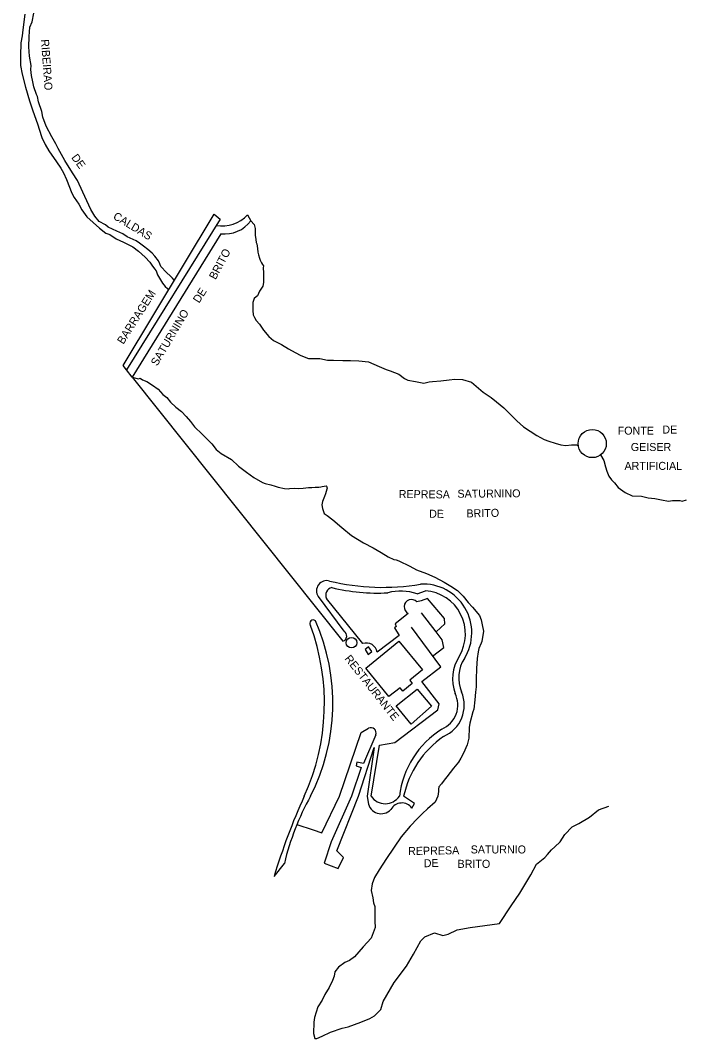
# Model space of a CAD drawing. Extents: x 325899 to 364828, y 7568995 to 7592502.
# Drawn here: x 339741 to 340074, y 7586381 to 7586890 of the extents above; entities that cross this region are included whole.
import ezdxf

# ---------------------------------------------------------------- set-up
doc = ezdxf.new("R2010")
doc.units = 0
for name, color, linetype in [('EDIFEXISTENT', 7, 'Continuous'), ('EDIFIDENTIF', 7, 'Continuous'), ('EDIFOBRAEXIS', 7, 'Continuous')]:
    doc.layers.add(name, color=color, linetype=linetype)

msp = doc.modelspace()

# ---------------------------------------------------------------- linework, layer by layer
at = {"layer": 'EDIFEXISTENT'}
for p, q in [((339792.51, 7586717.06), (339837.9, 7586792.71)), ((339837.9, 7586792.71), (339837.9, 7586792.71)), ((339837.9, 7586792.71), (339837.9, 7586792.71)), ((339837.9, 7586792.71), (339840.97, 7586790.2)), ((339854.7, 7586792.37), (339856.25, 7586789.42)), ((339840.97, 7586790.2), (339794.15, 7586714.93)), ((339841.37, 7586782.96), (339797.06, 7586711.32)), ((339792.51, 7586717.06), (339792.51, 7586717.06)), ((339794.15, 7586714.93), (339792.51, 7586717.06)), ((339797.06, 7586711.32), (339794.15, 7586714.93)), ((339913.76, 7586565.82), (339930.31, 7586579.38)), ((339930.31, 7586579.38), (339942.06, 7586565.04)), ((339925.28, 7586551.76), (339913.76, 7586565.82)), ((339942.06, 7586565.04), (339935.69, 7586559.82)), ((339937.01, 7586558.21), (339932.34, 7586554.38)), ((339935.69, 7586559.82), (339937.01, 7586558.21)), ((339930.97, 7586556.06), (339925.28, 7586551.76)), ((339932.34, 7586554.38), (339930.97, 7586556.06))]:
    msp.add_line(p, q, dxfattribs=at)
msp.add_circle((340026.92, 7586678.11), 7.03, dxfattribs=at)
for centre, radius, start, end in [((339841.76, 7586804.8), 17.94, 261.2223, 316.1329), ((339843.33, 7586798.82), 15.98, 262.9776, 323.9631)]:
    msp.add_arc(centre, radius, start, end, dxfattribs=at)
at = {"layer": 'EDIFOBRAEXIS'}
for points in [[(339743.36, 7586892.73), (339742.33, 7586884.86), (339741.95, 7586881.84), (339741.33, 7586878.4), (339741.21, 7586871.81), (339741.12, 7586867.04), (339741.96, 7586862.61), (339743.75, 7586856.21), (339745.67, 7586849.31), (339747.25, 7586844.92), (339749.77, 7586837.39), (339750.47, 7586835.17), (339751.91, 7586830.98), (339753.52, 7586827.6), (339755.3, 7586824.36), (339759.26, 7586818.94), (339761.35, 7586815.68), (339762.63, 7586813.39), (339764.16, 7586810.11), (339766.92, 7586803.28), (339768.08, 7586801.11), (339770.27, 7586797.65), (339771.8, 7586794.9), (339774.4, 7586791.34), (339780.69, 7586785.81), (339783.78, 7586783.3), (339785.86, 7586782.55), (339789.02, 7586780.35), (339792.73, 7586778.81), (339797.37, 7586776.35), (339800.15, 7586774.19), (339803.45, 7586771.23), (339805.76, 7586768.73), (339806.9, 7586767.32), (339808.2, 7586765.42), (339808.98, 7586764.41), (339809.73, 7586762.37), (339810.6, 7586760.68), (339812.19, 7586758.2), (339813.46, 7586756.52), (339814.62, 7586755.65), (339815.32, 7586755.1)], [(339818.03, 7586759.75), (339817.17, 7586760.75), (339816.22, 7586761.77), (339814.1, 7586763.51), (339811.38, 7586766.59), (339810.85, 7586767.95), (339810.19, 7586769.44), (339808.27, 7586771.69), (339807.07, 7586773.3), (339804.86, 7586775.11), (339802.72, 7586776.8), (339800.64, 7586778.31), (339799.02, 7586779.4), (339794.46, 7586781.46), (339792.38, 7586782.82), (339789.31, 7586784.21), (339784.95, 7586786.27), (339783.59, 7586787.36), (339780.46, 7586788.98), (339778.3, 7586791.72), (339776.31, 7586795.14), (339774.36, 7586799.34), (339772.33, 7586803.75), (339769.71, 7586809.57), (339767.18, 7586813.44), (339763.36, 7586819.57), (339759.98, 7586825.56), (339758.8, 7586827.9), (339756.78, 7586831.4), (339754.05, 7586836.68), (339752.42, 7586841.12), (339751.81, 7586844.01), (339750.18, 7586848.86), (339749.62, 7586851.57), (339749.25, 7586852.47), (339747.79, 7586856.28), (339747.33, 7586858.87), (339746.72, 7586862.08), (339746.39, 7586865.05), (339746.45, 7586867.05), (339745.66, 7586871.66), (339745.28, 7586876.36), (339745.44, 7586881.57), (339745.79, 7586886.22), (339747.06, 7586888.78), (339747.9, 7586893.24)], [(339856.25, 7586789.42), (339858.01, 7586787.6), (339858.47, 7586785.62), (339858.51, 7586782.17), (339858.82, 7586780.14), (339858.95, 7586778.55), (339859.22, 7586777.87), (339859.67, 7586775.51), (339859.85, 7586773.81), (339860.1, 7586772.47), (339860.59, 7586770.75), (339861.01, 7586769.69), (339861.69, 7586768.41), (339862.14, 7586767.58), (339862.71, 7586766.95), (339862.53, 7586765.83), (339862.6, 7586763.34), (339862.67, 7586760.65), (339862.7, 7586758.77), (339862.42, 7586757.65), (339862.31, 7586756.71), (339860.67, 7586754.29), (339859.59, 7586751.96), (339859.04, 7586751.45), (339857.97, 7586750.56), (339857.27, 7586748.54), (339857.35, 7586746.79), (339857.23, 7586744.61), (339857.47, 7586742.5), (339858.08, 7586741.04), (339859, 7586739.63), (339860.63, 7586737.83), (339862.71, 7586734.8), (339865.26, 7586731.59), (339867.58, 7586729.55), (339871.6, 7586727.59), (339875.17, 7586725.46), (339878.48, 7586723.57), (339881.33, 7586722.14), (339885.16, 7586720.66), (339888.13, 7586720.66), (339890.83, 7586720.66), (339894.7, 7586719.84), (339897.57, 7586719.81), (339902.3, 7586719.66), (339906.09, 7586719.53), (339910.3, 7586719.4), (339915.06, 7586718.87), (339920.36, 7586716.55), (339924, 7586715.09), (339925.86, 7586714.41), (339928.11, 7586713.61), (339930.23, 7586712.76), (339933.12, 7586710.55), (339934.83, 7586709.74), (339938.63, 7586709.05), (339942.78, 7586708.31), (339945.44, 7586708.89), (339947.06, 7586709.04), (339951.22, 7586709.42), (339955.4, 7586709.9), (339958.24, 7586710.31), (339962.05, 7586710.19), (339966.57, 7586708.83), (339972.4, 7586703.82), (339976.36, 7586701.15), (339979.14, 7586698.94), (339982.7, 7586695.98), (339989.19, 7586689.41), (339992.64, 7586686.5), (339999.2, 7586682.07), (340002.89, 7586680.12), (340005.19, 7586679.35), (340008.41, 7586678.31), (340011.19, 7586677.4), (340013.77, 7586677.06), (340016.63, 7586677.47), (340018.05, 7586677.44), (340019.12, 7586677.46), (340020.07, 7586676.99)], [(339797.06, 7586711.32), (339800.17, 7586710.49), (339801, 7586710.81), (339802.21, 7586710.01), (339804.29, 7586709.14), (339807.19, 7586707.36), (339809.99, 7586705.22), (339812.4, 7586702.57), (339814.28, 7586701.08), (339816.17, 7586698.85), (339818.78, 7586696.36), (339821.67, 7586694.15), (339823.95, 7586691.6), (339826.2, 7586689.07), (339828.1, 7586686.44), (339832.03, 7586682.77), (339836.89, 7586678.01), (339839.04, 7586675.15), (339841.49, 7586673.06), (339846.62, 7586670.12), (339850.06, 7586666.81), (339854.15, 7586663.73), (339857.81, 7586661.13), (339862.12, 7586658.66), (339863.47, 7586658.2), (339866.23, 7586657.41), (339868.45, 7586656.74), (339869.98, 7586656.39), (339873.06, 7586655.7), (339874.95, 7586655.51), (339875.71, 7586655.62), (339877.99, 7586655.81), (339880.15, 7586655.65), (339882.39, 7586655.74), (339883.73, 7586655.91), (339885.15, 7586656.09), (339886.82, 7586656.15), (339888.47, 7586656.25), (339890.25, 7586656.33), (339891.26, 7586656.43), (339891.9, 7586656.64), (339893.01, 7586656.86), (339893.97, 7586657.03), (339894.2, 7586656.78), (339894.5, 7586655.85), (339894.23, 7586655.26), (339893.56, 7586653.01), (339893.05, 7586651.68), (339892.18, 7586649.15), (339891.75, 7586647.44), (339892.09, 7586645.62), (339892.94, 7586643.12), (339894.46, 7586642.08), (339897.24, 7586639.97), (339901.83, 7586636.11), (339906.55, 7586632.13), (339912.61, 7586628.48), (339917.4, 7586625.97), (339921.38, 7586623.73), (339925.02, 7586621.56), (339927.74, 7586620.23), (339928.86, 7586619.95), (339930.31, 7586619.59), (339935.82, 7586616.85), (339939.08, 7586615.07), (339944.12, 7586613.26), (339948.24, 7586611.35), (339952.86, 7586608.79), (339956.32, 7586606.87), (339959.66, 7586604.74), (339962.45, 7586601.89), (339964.97, 7586598.74), (339967.07, 7586596.39), (339970.57, 7586592.21), (339971.4, 7586590.04), (339971.97, 7586587.61), (339972.59, 7586584.32), (339971.79, 7586579.27), (339971.35, 7586578.33), (339970.3, 7586575.77), (339969.85, 7586573.96), (339969.4, 7586570.67), (339969.1, 7586565.79), (339968.99, 7586560.33), (339968.86, 7586556.54), (339968.57, 7586553.84), (339968.31, 7586550.05), (339967.68, 7586545.47), (339967.32, 7586544.09), (339965.77, 7586538.37), (339965.4, 7586536.26), (339965.27, 7586530.97), (339964.39, 7586527.5), (339962.58, 7586523.48), (339961.2, 7586520.87), (339960.04, 7586518.94), (339957.58, 7586515.85), (339954.2, 7586511.6), (339952.88, 7586509.88), (339951.52, 7586508.1), (339950.25, 7586506.56), (339950.02, 7586505.46), (339950.06, 7586504.29), (339949.78, 7586501.91)], [(339797.06, 7586711.32), (339902.34, 7586579.4)], [(340031.09, 7586672.51), (340032.72, 7586669.57), (340033.56, 7586666.44), (340034.16, 7586664.26), (340035.16, 7586661.84), (340036.62, 7586660.06), (340038.09, 7586658.49), (340039.94, 7586656.11), (340043.41, 7586653.58), (340046.87, 7586652.06), (340051.57, 7586651.79), (340054.86, 7586650.93), (340058.15, 7586650.61), (340061.56, 7586649.91), (340065, 7586649.38), (340067, 7586649.6), (340069.42, 7586649.64), (340070.66, 7586649.66), (340071.93, 7586649.4), (340074.11, 7586650)], [(339939.42, 7586602.99), (339943.53, 7586604.56)], [(339889.99, 7586601.64), (339902.86, 7586584.37)], [(339912.29, 7586578.21), (339894.07, 7586600.75)], [(339948.9, 7586583.98), (339953.3, 7586587.99), (339953.05, 7586590.68), (339944.59, 7586600.77), (339941.41, 7586599.54), (339939.29, 7586598.97)], [(339934.97, 7586593.23), (339928.4, 7586588.04), (339928.88, 7586586.78), (339928.13, 7586586.08), (339930.43, 7586582.28), (339919.43, 7586573.84)], [(339947.17, 7586571.95), (339952.72, 7586576.14), (339951.86, 7586579.99), (339948.9, 7586583.98), (339941.61, 7586593.6)], [(339916.43, 7586501.91), (339920.65, 7586527.37), (339928.32, 7586528.78), (339949.78, 7586544.98), (339950.46, 7586547.99), (339941.71, 7586559.26), (339951.18, 7586566.49), (339936.56, 7586586.4)], [(339902.34, 7586579.4), (339902.34, 7586579.4)], [(339915.09, 7586576.58), (339913.41, 7586575.18), (339914.95, 7586572.72), (339916.76, 7586574.22), (339915.09, 7586576.58)], [(339939.46, 7586555.39), (339946.62, 7586546.93), (339936.47, 7586537.86), (339928.99, 7586547.03), (339928.99, 7586547.03)], [(339928.99, 7586547.03), (339939.46, 7586555.39)], [(339900.62, 7586501.91), (339911.37, 7586533.79), (339915.17, 7586535.96)], [(339918.81, 7586532.6), (339912.61, 7586518.17), (339909.24, 7586518.84), (339908.94, 7586517.11), (339911.4, 7586516.21), (339906.56, 7586501.91)], [(339910.05, 7586501.91), (339918, 7586526.18), (339914.39, 7586501.91)], [(339879.36, 7586487.82), (339887.53, 7586485.1), (339891.75, 7586483.54), (339900.62, 7586501.91)], [(339949.78, 7586501.91), (339948.39, 7586498.86), (339944.65, 7586495.67), (339942.04, 7586493.23), (339939.59, 7586490.7), (339935.89, 7586487), (339931.4, 7586481.66), (339924.05, 7586470.7), (339920.45, 7586465.17), (339918.17, 7586461.29), (339916.95, 7586458.04), (339916.47, 7586454.72), (339917.22, 7586451.04), (339917.67, 7586448.56), (339918.23, 7586446.76), (339918.27, 7586444.4), (339918.33, 7586439.41), (339918.38, 7586436.36), (339916.49, 7586431.01), (339912.51, 7586426.62), (339908.17, 7586421.66), (339905.55, 7586419.79), (339903.23, 7586418.78), (339900.16, 7586416.44), (339898.29, 7586414.17), (339897.97, 7586411.93), (339897.07, 7586409.75), (339895.52, 7586406.31), (339893.29, 7586402.79), (339891.96, 7586400.02), (339889.78, 7586396.68), (339888.09, 7586391.36), (339887.82, 7586388.94), (339887.69, 7586383.36), (339888.34, 7586380.86), (339889.23, 7586380.77), (339892.03, 7586382.01), (339896.15, 7586383.99), (339901.97, 7586386.02), (339904.88, 7586386.62), (339911.25, 7586388.92), (339915.7, 7586390.9), (339918.04, 7586392.16), (339921.25, 7586395.39), (339922.48, 7586399.33), (339927.92, 7586408.78), (339934.1, 7586416.95), (339937.66, 7586423.01), (339941.34, 7586429.64), (339943.34, 7586431.58), (339948.09, 7586433.67), (339952.29, 7586432.26), (339954.92, 7586432.97), (339959.39, 7586435.1), (339965.86, 7586436.25), (339980.66, 7586438.3), (339986.41, 7586447.18), (339990.79, 7586453.48), (339996.26, 7586462.66), (339998.99, 7586467.89), (340003.31, 7586471.25), (340004.59, 7586472.79), (340006.58, 7586475.06), (340008.24, 7586476.62), (340010.92, 7586479.08), (340013.17, 7586482.73), (340016.93, 7586486.53), (340020.23, 7586488.32), (340025.62, 7586491.41), (340029.99, 7586495.17), (340035.28, 7586496.99)], [(339906.56, 7586501.91), (339896.38, 7586479.17), (339892.99, 7586468.5), (339899.91, 7586465.72), (339902.59, 7586471.33), (339899.25, 7586474.53), (339910.05, 7586501.91)], [(339914.39, 7586501.91), (339914.87, 7586498.83)], [(339936.81, 7586495.94), (339938.17, 7586498.25), (339932.66, 7586501.91)], [(339867.89, 7586461.75), (339873.07, 7586468.35)]]:
    msp.add_lwpolyline(points, dxfattribs=at)
msp.add_circle((339906.6, 7586578.61), 2.65, dxfattribs=at)
for centre, radius, start, end in [((339894.22, 7586604.52), 5.11, 73.2112, 214.2085), ((339922.1, 7586718.48), 112.22, 256.3881, 279.7124), ((339942.42, 7586583.59), 24.32, 328.108, 93.2695), ((339897.55, 7586602.37), 3.84, 102.1762, 204.9657), ((339919.72, 7586702.12), 98.71, 256.5369, 272.9358), ((339931.2, 7586579.63), 24.77, 70.6176, 105.0275), ((339941.93, 7586583), 21.62, 328.6027, 85.7562), ((339936.59, 7586596.51), 3.65, 42.3728, 243.7043), ((339781.48, 7586548.33), 111.61, 335.4225, 20.4199), ((339887.5, 7586588.23), 1.72, 51.3089, 213.847), ((339795.42, 7586548.27), 101.89, 332.9383, 23.9108), ((339901.49, 7586582), 2.74, 288.1865, 59.7852), ((339913.99, 7586572.96), 5.51, 9.0896, 107.946), ((339978.48, 7586560.42), 21.33, 147.9855, 199.5552), ((339978.16, 7586561.06), 17.93, 147.3225, 203.0189), ((339946.81, 7586547.42), 12.96, 292.4109, 26.8712), ((339945.82, 7586547.47), 17.15, 293.2923, 22.553), ((339916.17, 7586533.4), 2.75, 343.0091, 111.4864), ((339976.77, 7586496.11), 46.61, 122.4682, 172.8491), ((339980.37, 7586491.56), 48.82, 124.6671, 167.7616), ((340188.54, 7586364.24), 335.15, 155.7459, 163.0848), ((340000.8, 7586437.88), 131.31, 150.8132, 166.5814), ((339923.48, 7586506.63), 8.48, 213.817, 326.183), ((339921.46, 7586499.83), 6.67, 188.6169, 316.5936), ((339931.77, 7586492.31), 6.21, 35.8459, 151.7041)]:
    msp.add_arc(centre, radius, start, end, dxfattribs=at)

# ---------------------------------------------------------------- texts
at = {"layer": 'EDIFIDENTIF'}
for s, rotation, p in [('RIBEIRAO', 274.1726, (339751.41, 7586879.97)), ('DE', 306.0466, (339766.39, 7586821)), ('CALDAS', 328.6983, (339787.1, 7586790.67)), ('BRITO', 61.9478, (339838.69, 7586759.71)), ('BARRAGEM', 57.5556, (339792.57, 7586727.4)), ('DE', 57.5162, (339830.45, 7586747.98)), ('SATURNINO', 59.3856, (339809.49, 7586716.55)), ('REPRESA', 359.4507, (339930.21, 7586650.9)), ('SATURNINO', 0.3929, (339959.58, 7586651.03)), ('DE', 359.3888, (339945.39, 7586641.06)), ('BRITO', 1.2462, (339964.11, 7586641.18)), ('RESTAURANTE', 308.2311, (339902.95, 7586570.54)), ('REPRESA', 0.9386, (339934.92, 7586472.51)), ('DE', 1.3011, (339942.75, 7586466.4))]:
    msp.add_text(s, height=4, rotation=rotation, dxfattribs=at).set_placement(p)
for s, p in [('FONTE', (340039.64, 7586682.55)), ('DE', (340061.96, 7586683.11)), ('GEISER', (340046.21, 7586674.38)), ('ARTIFICIAL', (340043.04, 7586664.95)), ('SATURNIO', (339966.19, 7586473.3)), ('BRITO', (339959.61, 7586466.11))]:
    msp.add_text(s, height=4, dxfattribs=at).set_placement(p)

doc.saveas('drawing.dxf')
